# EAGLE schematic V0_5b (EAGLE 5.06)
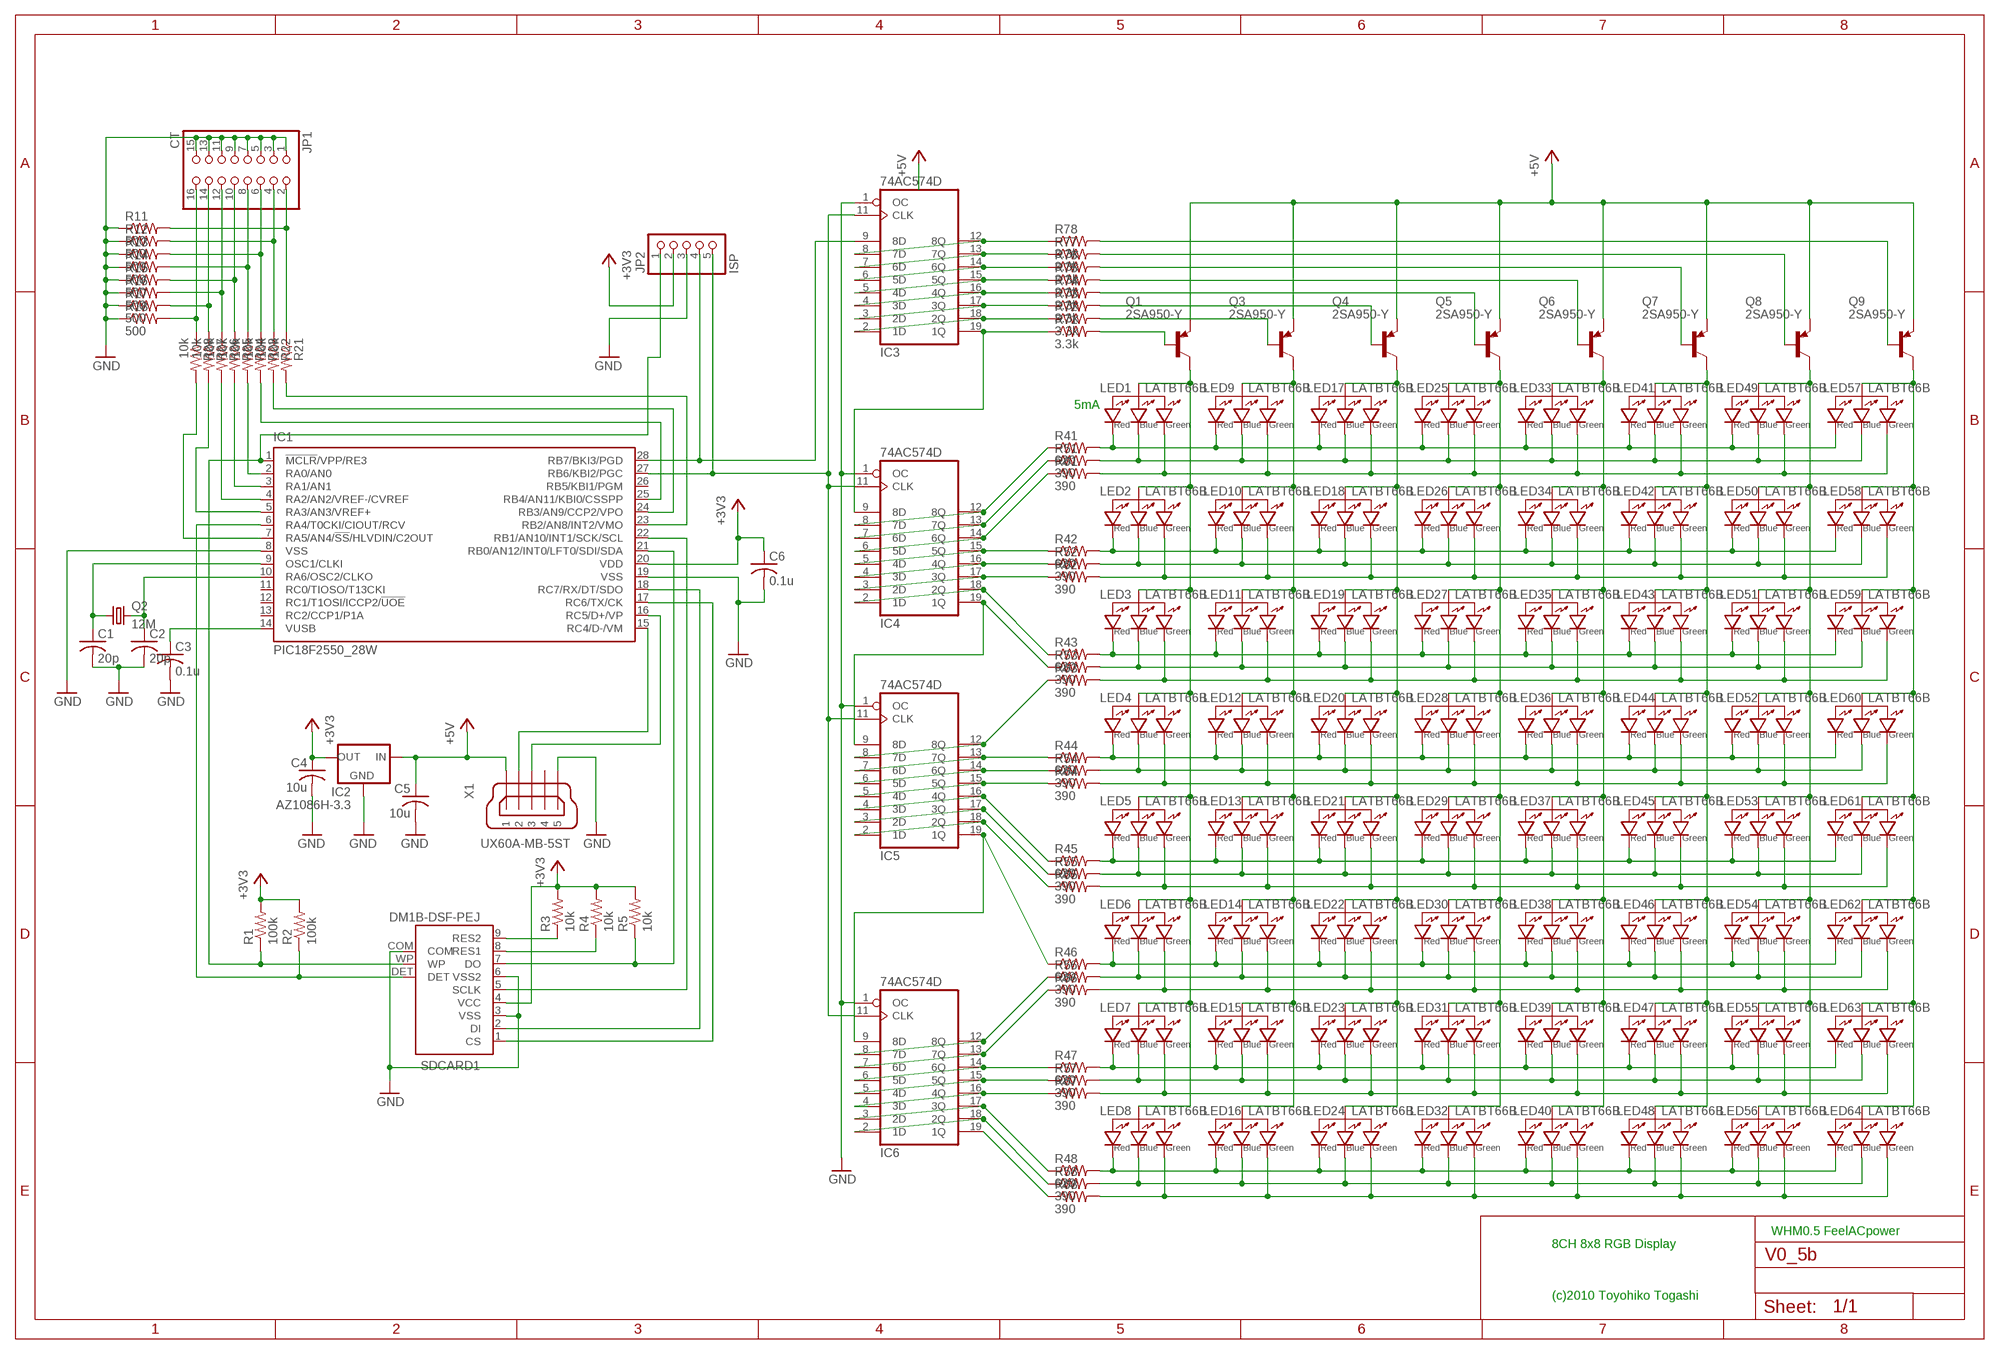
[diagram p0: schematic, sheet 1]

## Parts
C1  20p  C-USC0603  [C0603]
C2  20p  C-USC0603  [C0603]
C3  0.1u  C-USC0603  [C0603]
C4  10u  C-USC1206  [C1206]
C5  10u  C-USC1206  [C1206]
C6  0.1u  C-USC0603  [C0603]
IC1  PIC18F2550_28W  [SO28W]
IC2  AZ1086H-3.3  XC63FPP  [SOT89R]
IC3  74AC574D  [SO20W]
IC4  74AC574D  [SO20W]
IC5  74AC574D  [SO20W]
IC6  74AC574D  [SO20W]
JP1  CT  PINHD-2X8  [2X08]
JP2  ISP  PINHD-1X5  [1X05]
LED1  LATBT66B  [P-LCC-4]
LED2  LATBT66B  [P-LCC-4]
LED3  LATBT66B  [P-LCC-4]
LED4  LATBT66B  [P-LCC-4]
LED5  LATBT66B  [P-LCC-4]
LED6  LATBT66B  [P-LCC-4]
LED7  LATBT66B  [P-LCC-4]
LED8  LATBT66B  [P-LCC-4]
LED9  LATBT66B  [P-LCC-4]
LED10  LATBT66B  [P-LCC-4]
LED11  LATBT66B  [P-LCC-4]
LED12  LATBT66B  [P-LCC-4]
LED13  LATBT66B  [P-LCC-4]
LED14  LATBT66B  [P-LCC-4]
LED15  LATBT66B  [P-LCC-4]
LED16  LATBT66B  [P-LCC-4]
LED17  LATBT66B  [P-LCC-4]
LED18  LATBT66B  [P-LCC-4]
LED19  LATBT66B  [P-LCC-4]
LED20  LATBT66B  [P-LCC-4]
LED21  LATBT66B  [P-LCC-4]
LED22  LATBT66B  [P-LCC-4]
LED23  LATBT66B  [P-LCC-4]
LED24  LATBT66B  [P-LCC-4]
LED25  LATBT66B  [P-LCC-4]
LED26  LATBT66B  [P-LCC-4]
LED27  LATBT66B  [P-LCC-4]
LED28  LATBT66B  [P-LCC-4]
LED29  LATBT66B  [P-LCC-4]
LED30  LATBT66B  [P-LCC-4]
LED31  LATBT66B  [P-LCC-4]
LED32  LATBT66B  [P-LCC-4]
LED33  LATBT66B  [P-LCC-4]
LED34  LATBT66B  [P-LCC-4]
LED35  LATBT66B  [P-LCC-4]
LED36  LATBT66B  [P-LCC-4]
LED37  LATBT66B  [P-LCC-4]
LED38  LATBT66B  [P-LCC-4]
LED39  LATBT66B  [P-LCC-4]
LED40  LATBT66B  [P-LCC-4]
LED41  LATBT66B  [P-LCC-4]
LED42  LATBT66B  [P-LCC-4]
LED43  LATBT66B  [P-LCC-4]
LED44  LATBT66B  [P-LCC-4]
LED45  LATBT66B  [P-LCC-4]
LED46  LATBT66B  [P-LCC-4]
LED47  LATBT66B  [P-LCC-4]
LED48  LATBT66B  [P-LCC-4]
LED49  LATBT66B  [P-LCC-4]
LED50  LATBT66B  [P-LCC-4]
LED51  LATBT66B  [P-LCC-4]
LED52  LATBT66B  [P-LCC-4]
LED53  LATBT66B  [P-LCC-4]
LED54  LATBT66B  [P-LCC-4]
LED55  LATBT66B  [P-LCC-4]
LED56  LATBT66B  [P-LCC-4]
LED57  LATBT66B  [P-LCC-4]
LED58  LATBT66B  [P-LCC-4]
LED59  LATBT66B  [P-LCC-4]
LED60  LATBT66B  [P-LCC-4]
LED61  LATBT66B  [P-LCC-4]
LED62  LATBT66B  [P-LCC-4]
LED63  LATBT66B  [P-LCC-4]
LED64  LATBT66B  [P-LCC-4]
Q1  2SA950-Y  2N3906  [TO92]
Q2  12M  CRYSTALHC49S  [HC49/S]
Q3  2SA950-Y  2N3906  [TO92]
Q4  2SA950-Y  2N3906  [TO92]
Q5  2SA950-Y  2N3906  [TO92]
Q6  2SA950-Y  2N3906  [TO92]
Q7  2SA950-Y  2N3906  [TO92]
Q8  2SA950-Y  2N3906  [TO92]
Q9  2SA950-Y  2N3906  [TO92]
R1  100k  R-US_R0603  [R0603]
R2  100k  R-US_R0603  [R0603]
R3  10k  R-US_R0603  [R0603]
R4  10k  R-US_R0603  [R0603]
R5  10k  R-US_R0603  [R0603]
R11  500  R-US_R0603  [R0603]
R12  500  R-US_R0603  [R0603]
R13  500  R-US_R0603  [R0603]
R14  500  R-US_R0603  [R0603]
R15  500  R-US_R0603  [R0603]
R16  500  R-US_R0603  [R0603]
R17  500  R-US_R0603  [R0603]
R18  500  R-US_R0603  [R0603]
R21  10k  R-US_R0603  [R0603]
R22  10k  R-US_R0603  [R0603]
R23  10k  R-US_R0603  [R0603]
R24  10k  R-US_R0603  [R0603]
R25  10k  R-US_R0603  [R0603]
R26  10k  R-US_R0603  [R0603]
R27  10k  R-US_R0603  [R0603]
R28  10k  R-US_R0603  [R0603]
R41  620  R-US_R0603  [R0603]
R42  620  R-US_R0603  [R0603]
R43  620  R-US_R0603  [R0603]
R44  620  R-US_R0603  [R0603]
R45  620  R-US_R0603  [R0603]
R46  620  R-US_R0603  [R0603]
R47  620  R-US_R0603  [R0603]
R48  620  R-US_R0603  [R0603]
R51  390  R-US_R0603  [R0603]
R52  390  R-US_R0603  [R0603]
R53  390  R-US_R0603  [R0603]
R54  390  R-US_R0603  [R0603]
R55  390  R-US_R0603  [R0603]
R56  390  R-US_R0603  [R0603]
R57  390  R-US_R0603  [R0603]
R58  390  R-US_R0603  [R0603]
R61  390  R-US_R0603  [R0603]
R62  390  R-US_R0603  [R0603]
R63  390  R-US_R0603  [R0603]
R64  390  R-US_R0603  [R0603]
R65  390  R-US_R0603  [R0603]
R66  390  R-US_R0603  [R0603]
R67  390  R-US_R0603  [R0603]
R68  390  R-US_R0603  [R0603]
R71  3.3k  R-US_R0603  [R0603]
R72  3.3k  R-US_R0603  [R0603]
R73  3.3k  R-US_R0603  [R0603]
R74  3.3k  R-US_R0603  [R0603]
R75  3.3k  R-US_R0603  [R0603]
R76  3.3k  R-US_R0603  [R0603]
R77  3.3k  R-US_R0603  [R0603]
R78  3.3k  R-US_R0603  [R0603]
SDCARD1  DM1B-DSF-PEJ  [DM1B]
X1  UX60A-MB-5ST  MINI-USB-SHIELD-UX60A-MB-5ST  [UX60A-MB-5ST]

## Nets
+3V3: C4.1 C6.1 IC1.20(VDD) IC2.3(OUT) JP2.2 R1.2 R2.2 R3.2 R4.2 R5.2 SDCARD1.4(VCC)
+5V: C5.1 IC2.2(IN) Q1.3(E) Q3.3(E) Q4.3(E) Q5.3(E) Q6.3(E) Q7.3(E) Q8.3(E) Q9.3(E) X1.1
GND: C1.2 C2.2 C3.2 C4.2 C5.2 C6.2 IC1.8(VSS) IC1.19(VSS) IC2.1(GND) IC3.1(OC) IC4.1(OC) IC5.1(OC) IC6.1(OC) JP1.1 JP1.3 JP1.5 JP1.7 JP1.9 JP1.11 JP1.13 JP1.15 JP2.3 R11.1 R12.1 R13.1 R14.1 R15.1 R16.1 R17.1 R18.1 SDCARD1.3(VSS) SDCARD1.6(VSS2) SDCARD1.COM X1.5
N$1: IC1.2(RA0/AN0) R24.2
N$2: IC1.3(RA1/AN1) R25.2
N$3: IC1.4(RA2/AN2/VREF-/CVREF) R26.2
N$4: IC1.5(RA3/AN3/VREF+) R27.2
N$5: JP1.8 R14.2 R24.1
N$6: IC1.22(RB1/AN10/INT1/SCK/SCL) SDCARD1.5(SCLK)
N$7: IC1.21(RB0/AN12/INT0/LFT0/SDI/SDA) R5.1 SDCARD1.7(DO)
N$8: IC1.18(RC7/RX/DT/SDO) SDCARD1.2(DI)
N$9: IC1.17(RC6/TX/CK) SDCARD1.1(CS)
N$10: IC1.1(!MCLR!/VPP/RE3) JP2.1 R1.1 SDCARD1.WP
N$11: IC6.19(1Q) R68.1
N$14: IC3.2(1D) IC3.18(2Q) R72.1
N$15: IC1.28(RB7/BKI3/PGD) IC3.9(8D) JP2.4
N$16: IC1.15(RC4/D-/VM) X1.2
N$17: IC1.16(RC5/D+/VP) X1.3
N$18: LED2.P$1 LED10.P$1 LED18.P$1 LED26.P$1 LED34.P$1 LED42.P$1 LED50.P$1 LED58.P$1 R42.2
N$19: LED2.P$3 LED10.P$3 LED18.P$3 LED26.P$3 LED34.P$3 LED42.P$3 LED50.P$3 LED58.P$3 R52.2
N$20: LED2.P$4 LED10.P$4 LED18.P$4 LED26.P$4 LED34.P$4 LED42.P$4 LED50.P$4 LED58.P$4 R62.2
N$21: LED1.P$3 LED9.P$3 LED17.P$3 LED25.P$3 LED33.P$3 LED41.P$3 LED49.P$3 LED57.P$3 R51.2
N$22: LED1.P$4 LED9.P$4 LED17.P$4 LED25.P$4 LED33.P$4 LED41.P$4 LED49.P$4 LED57.P$4 R61.2
N$23: JP1.6 R13.2 R23.1
N$24: JP1.4 R12.2 R22.1
N$25: JP1.2 R11.2 R21.1
N$26: IC3.3(2D) IC3.17(3Q) R73.1
N$27: IC3.4(3D) IC3.16(4Q) R74.1
N$28: IC3.5(4D) IC3.15(5Q) R75.1
N$29: IC1.25(RB4/AN11/KBI0/CSSPP) R23.2
N$32: IC1.24(RB3/AN9/CCP2/VPO) R22.2
N$33: IC3.6(5D) IC3.14(6Q) R76.1
N$34: IC1.23(RB2/AN8/INT2/VMO) R21.2
N$35: LED3.P$3 LED11.P$3 LED19.P$3 LED27.P$3 LED35.P$3 LED43.P$3 LED51.P$3 LED59.P$3 R53.2
N$36: LED7.P$4 LED15.P$4 LED23.P$4 LED31.P$4 LED39.P$4 LED47.P$4 LED55.P$4 LED63.P$4 R67.2
N$37: LED8.P$4 LED16.P$4 LED24.P$4 LED32.P$4 LED40.P$4 LED48.P$4 LED56.P$4 LED64.P$4 R68.2
N$38: IC4.8(7D) IC4.12(8Q) R41.1
N$39: IC4.7(6D) IC4.13(7Q) R51.1
N$40: IC4.6(5D) IC4.14(6Q) R61.1
N$41: JP1.10 R15.2 R25.1
N$42: R3.1 SDCARD1.9(RES2)
N$43: R4.1 SDCARD1.8(RES1)
N$44: JP1.12 R16.2 R26.1
N$45: JP1.14 R17.2 R27.1
N$46: JP1.16 R18.2 R28.1
N$47: C2.1 IC1.10(RA6/OSC2/CLKO) Q2.2
N$48: IC3.7(6D) IC3.13(7Q) R77.1
N$49: C1.1 IC1.9(OSC1/CLKI) Q2.1
N$50: IC1.7(RA5/AN4/!SS!/HLVDIN/C2OUT) R28.2
N$51: IC1.6(RA4/T0CKI/CIOUT/RCV) R2.1 SDCARD1.DET
N$52: C3.1 IC1.14(VUSB)
N$53: IC3.8(7D) IC3.12(8Q) R78.1
N$54: IC3.19(1Q) IC4.9(8D) R71.1
N$55: LED1.P$2 LED2.P$2 LED3.P$2 LED4.P$2 LED5.P$2 LED6.P$2 LED7.P$2 LED8.P$2 Q1.1(C)
N$56: IC4.5(4D) IC4.15(5Q) R42.1
N$57: IC4.4(3D) IC4.16(4Q) R52.1
N$58: IC4.3(2D) IC4.17(3Q) R62.1
N$59: IC4.2(1D) IC4.18(2Q) R43.1
N$60: IC4.19(1Q) IC5.9(8D) R53.1
N$61: IC5.8(7D) IC5.12(8Q) R63.1
N$62: IC5.7(6D) IC5.13(7Q) R44.1
N$63: IC5.6(5D) IC5.14(6Q) R54.1
N$64: IC5.5(4D) IC5.15(5Q) R64.1
N$65: IC5.4(3D) IC5.16(4Q) R45.1
N$66: IC5.3(2D) IC5.17(3Q) R55.1
N$67: IC5.2(1D) IC5.18(2Q) R65.1
N$68: IC5.19(1Q) IC6.9(8D) R46.1
N$69: IC6.8(7D) IC6.12(8Q) R56.1
N$70: IC6.7(6D) IC6.13(7Q) R66.1
N$71: IC6.6(5D) IC6.14(6Q) R47.1
N$72: IC6.5(4D) IC6.15(5Q) R57.1
N$73: IC6.4(3D) IC6.16(4Q) R67.1
N$74: IC6.3(2D) IC6.17(3Q) R48.1
N$75: IC6.2(1D) IC6.18(2Q) R58.1
N$77: LED1.P$1 LED9.P$1 LED17.P$1 LED25.P$1 LED33.P$1 LED41.P$1 LED49.P$1 LED57.P$1 R41.2
N$78: LED3.P$1 LED11.P$1 LED19.P$1 LED27.P$1 LED35.P$1 LED43.P$1 LED51.P$1 LED59.P$1 R43.2
N$79: LED3.P$4 LED11.P$4 LED19.P$4 LED27.P$4 LED35.P$4 LED43.P$4 LED51.P$4 LED59.P$4 R63.2
N$80: LED4.P$1 LED12.P$1 LED20.P$1 LED28.P$1 LED36.P$1 LED44.P$1 LED52.P$1 LED60.P$1 R44.2
N$81: LED4.P$3 LED12.P$3 LED20.P$3 LED28.P$3 LED36.P$3 LED44.P$3 LED52.P$3 LED60.P$3 R54.2
N$82: LED4.P$4 LED12.P$4 LED20.P$4 LED28.P$4 LED36.P$4 LED44.P$4 LED52.P$4 LED60.P$4 R64.2
N$83: LED5.P$1 LED13.P$1 LED21.P$1 LED29.P$1 LED37.P$1 LED45.P$1 LED53.P$1 LED61.P$1 R45.2
N$84: LED5.P$3 LED13.P$3 LED21.P$3 LED29.P$3 LED37.P$3 LED45.P$3 LED53.P$3 LED61.P$3 R55.2
N$85: LED5.P$4 LED13.P$4 LED21.P$4 LED29.P$4 LED37.P$4 LED45.P$4 LED53.P$4 LED61.P$4 R65.2
N$86: LED6.P$1 LED14.P$1 LED22.P$1 LED30.P$1 LED38.P$1 LED46.P$1 LED54.P$1 LED62.P$1 R46.2
N$87: LED6.P$3 LED14.P$3 LED22.P$3 LED30.P$3 LED38.P$3 LED46.P$3 LED54.P$3 LED62.P$3 R56.2
N$88: LED6.P$4 LED14.P$4 LED22.P$4 LED30.P$4 LED38.P$4 LED46.P$4 LED54.P$4 LED62.P$4 R66.2
N$89: LED7.P$1 LED15.P$1 LED23.P$1 LED31.P$1 LED39.P$1 LED47.P$1 LED55.P$1 LED63.P$1 R47.2
N$90: LED7.P$3 LED15.P$3 LED23.P$3 LED31.P$3 LED39.P$3 LED47.P$3 LED55.P$3 LED63.P$3 R57.2
N$91: LED8.P$1 LED16.P$1 LED24.P$1 LED32.P$1 LED40.P$1 LED48.P$1 LED56.P$1 LED64.P$1 R48.2
N$92: LED8.P$3 LED16.P$3 LED24.P$3 LED32.P$3 LED40.P$3 LED48.P$3 LED56.P$3 LED64.P$3 R58.2
N$93: LED57.P$2 LED58.P$2 LED59.P$2 LED60.P$2 LED61.P$2 LED62.P$2 LED63.P$2 LED64.P$2 Q9.1(C)
N$94: LED49.P$2 LED50.P$2 LED51.P$2 LED52.P$2 LED53.P$2 LED54.P$2 LED55.P$2 LED56.P$2 Q8.1(C)
N$95: LED41.P$2 LED42.P$2 LED43.P$2 LED44.P$2 LED45.P$2 LED46.P$2 LED47.P$2 LED48.P$2 Q7.1(C)
N$96: LED33.P$2 LED34.P$2 LED35.P$2 LED36.P$2 LED37.P$2 LED38.P$2 LED39.P$2 LED40.P$2 Q6.1(C)
N$97: LED25.P$2 LED26.P$2 LED27.P$2 LED28.P$2 LED29.P$2 LED30.P$2 LED31.P$2 LED32.P$2 Q5.1(C)
N$98: LED17.P$2 LED18.P$2 LED19.P$2 LED20.P$2 LED21.P$2 LED22.P$2 LED23.P$2 LED24.P$2 Q4.1(C)
N$99: LED9.P$2 LED10.P$2 LED11.P$2 LED12.P$2 LED13.P$2 LED14.P$2 LED15.P$2 LED16.P$2 Q3.1(C)
N$100: Q1.2(B) R71.2
N$101: Q3.2(B) R72.2
N$102: Q4.2(B) R73.2
N$103: Q5.2(B) R74.2
N$104: Q6.2(B) R75.2
N$105: Q7.2(B) R76.2
N$106: Q8.2(B) R77.2
N$107: Q9.2(B) R78.2
N$109: IC1.27(RB6/KBI2/PGC) IC3.11(CLK) IC4.11(CLK) IC5.11(CLK) IC6.11(CLK) JP2.5
Unconnected: IC1.11(RC0/TIOSO/T13CKI) IC1.12(RC1/T1OSI/ICCP2/!UOE) IC1.13(RC2/CCP1/P1A) IC1.26(RB5/KBI1/PGM) X1.4 X1.M1(S1) X1.M2(S2) X1.M3(S3) X1.M4(S4)

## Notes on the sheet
- 5mA
- WHM0.5 FeelACpower
- 8CH 8x8 RGB Display
- (c)2010 Toyohiko Togashi

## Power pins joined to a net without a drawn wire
GND: IC3.10(GND) IC4.10(GND) IC5.10(GND) IC6.10(GND)
VCC: IC3.20(VCC) IC4.20(VCC) IC5.20(VCC) IC6.20(VCC)

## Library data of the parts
C1-C6 = rcl:C-US: CAPACITOR, American symbol
IC1 = microchip:PIC18F2*_28: USB Microcontrollers with nanoWatt Technology High-Performance, Enhanced Flash, 28/40/44-Pin, Source: http://ww1.microchip.com/downloads/en/devicedoc/39632c.pdf
IC2 = v-reg:XC63FP: Positiv Voltage Regulators www.torex.co.jp/english/product/pro02/pdf/0201_xc62fp.pdf
IC3-IC6 = 74xx-eu:74*574: 8-bit D type FLIP FLOP bus driver
JP1 = pinhead:PINHD-2X8: PIN HEADER
JP2 = pinhead:PINHD-1X5: PIN HEADER
LED1-LED64 = TOG:LATBT66B: RGB LED SMD
Q1 Q3-Q9 = transistor-pnp:2N3906: PNP Transistor
Q2 = crystal:CRYSTAL: CRYSTAL
R1-R5 R11-R18 R21-R28 R41-R48 R51-R58 R61-R68 R71-R78 = rcl:R-US_: RESISTOR, American symbol
SDCARD1 = TOG:DM1B-DSF-PEJ: SDcard connector reverse type HIROSE
X1 = con-hirose:MINI-USB-SHIELD-: MINI USB Connector Source: http://www.hirose.co.jp/cataloge_hp/e24000019.pdf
